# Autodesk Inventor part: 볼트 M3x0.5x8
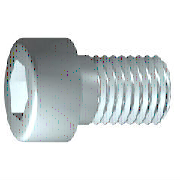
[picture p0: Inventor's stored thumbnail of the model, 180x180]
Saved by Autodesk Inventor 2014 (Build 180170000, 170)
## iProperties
IsCustomPart: 1
Company: 한국ATC센터
Created: 2015-12
Part Number: 볼트 M3x0.5x8
Material: 스테인리스강
Description: 6각머리 태핑 나사
Document SubType Name: Modeling
Standard: KS B 1003
Designer: mdu
Standards Organization: KS
Language: ko-KR
Size Designation: M 4 x 12
Categories: <MemberInstance><Categories><Category DisplayName="조임쇠" InternalName="e4da775c-781d-43d5-af7c-5136215cf5a6" Mnemonic="FSTN"><Category DisplayName="볼트" InternalN
Density: 8.08 g/cm^3
Mass: 1.41278 g
Surface Area: 2.58399 cm^2
Volume: 0.174849 cm^3
Appearance: 반광택
Author: mdu
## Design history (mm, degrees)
sketch "스케치1"
  geometry: L1 (-0.867, 0)-(16, 0); L2 (16, 0)-(16, 1.5); L3 (16, 1.5)-(1.25, 1.5); L4 (1.25, 1.5)-(0.943, 1.5); L5 (0.943, 1.5)-(0, 1.5); L6 (0, 1.5)-(0, 2.75); L7 (0, 2.75)-(-3, 2.75); L8 (-3, 2.75)-(-3, 1.443); L9 (-3, 1.443)-(-1.7, 1.443); L10 (-1.7, 1.443)-(-0.867, 0); L11 (-6.8, 0)-(19.8, 0) reference; L12 (0, -0.55)-(0, 3.3) reference; L13 (1.25, 1.5)-(0, 1.5)
  constraints: 22 end point, 6 parallel, 2 collinear, 2 perpendicular, 1 horizontal, 1 point on line
  dimensions: "d1" = 14.75 distance from line of L3.end L2 (= GEL); "d2" = 0.30683 distance of L4.end L3.end (computed from GAL); "d3" = 3 distance between parallel lines of L8 L6 (= KOH); "d4" = 1.3 distance of L8.end L9.end (= INTI); "d5" = 60 deg angle of L10 L1; "d6" = 3 diameter of L3 L1 (= GD); "d7" = 3 diameter of L5 L1 (= BDM); "d8" = 2.88675 diameter of L9 L1 (= 1.1547 x SW); "d9" = 5.5 diameter of L7 L1 (= KOD); "d26" = 16 distance between parallel lines of L12 L2 (= NLG)
revolve "본체" sketch "스케치1" stored, may be unused: angle "d10" = 90 deg
sketch "스케치2"
  geometry: L1 (0, -3.85)-(0, 3.85) reference; L2 (-3.85, 0)-(3.85, 0) reference; L3 (1.443, 0)-(0.722, -1.25); L4 (0.722, -1.25)-(-0.722, -1.25); L5 (-0.722, -1.25)-(-1.443, 0); L6 (-1.443, 0)-(-0.722, 1.25); L7 (-0.722, 1.25)-(0.722, 1.25); L8 (0.722, 1.25)-(1.443, 0); 2 further points
  constraints: 12 end point, 1 coincident, 1 horizontal alignment, 1 point on line, 12 other
extrude "슬롯" join sketch "스케치2" stored distance "d11" = 10; taper "d12" = 0 deg
workplane "Work Plane1"
fillet "Fillet2" dims "d30" = 0.1 (= R)
body "Solid1"
fillet "모깎기1" dims "d17" = 0.3 (= RR)
feature "스레드" dims "d13" = 14.75 (= GEL), "d14" = 0
chamfer "모따기1" distance "d15" = 0.30673 (= -0.5 x SPD + 0.5 x GD); stored, may be unused: second distance "d16" = 0.30673 (= GUL), angle "d27" = 45 deg
other parameters: "GD" = 3 (= NND) [user parameter; used in 2 equation terms], "NLG" = 16 [user parameter; used in 1 equation term], "GEL" = 14.75 [user parameter; used in 2 equation terms], "KOD" = 5.5 [user parameter; used in 1 equation term], "KOH" = 3 [user parameter; used in 1 equation term], "INTI" = 1.3 [user parameter; used in 1 equation term], "GAL" = 0.30673 (= 0.61345 x PTC) [user parameter; used in 1 equation term], "GUL" = 0.30673 (= 0.61345 x PTC) [user parameter; used in 1 equation term], "BDM" = 3 (= NND) [user parameter; used in 1 equation term], "SW" = 2.5 [user parameter; used in 2 equation terms], "RR" = 0.3 [user parameter; used in 1 equation term], "SPD" = 2.38655 (= NND - 1.2269 x PTC) [user parameter; used in 1 equation term], "d19" = 0, "d28" = 0, "d29" = 0, "R" = 0.1 [user parameter; used in 1 equation term], "PHH" = 0.1 [user parameter], "GD1" = 2.38655 (= THREADDIA - 1.2269 x PTC) [user parameter], "THREADDIA" = 3 [user parameter; used in 1 equation term], "FAWI" = 45 deg [user parameter], "PTC" = 0.5 [user parameter; used in 5 equation terms], "NND" = 3 [user parameter; used in 3 equation terms], "TOA" = 30 deg [user parameter], "E0" = 2.8875 (= 1.155 x SW) [user parameter]
